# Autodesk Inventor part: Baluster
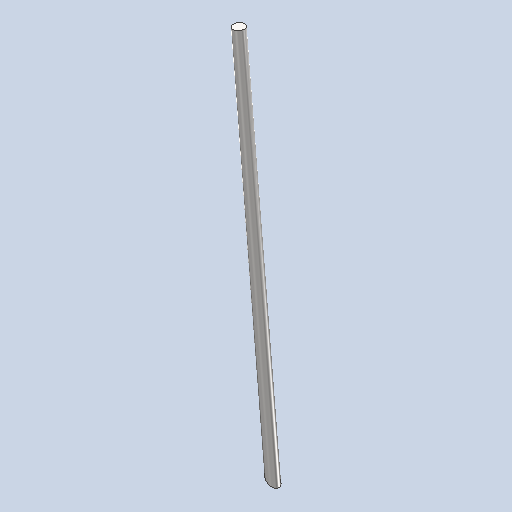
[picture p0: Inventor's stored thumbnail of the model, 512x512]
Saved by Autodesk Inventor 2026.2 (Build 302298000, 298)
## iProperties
Created: 2022-06
Part Number: Baluster
Material: Steel, Galvanized
Document SubType Name: Modeling
Designer: reaumed
Density: 7.85 g/cm^3
Appearance: Galvanized
Mass: 3323.97 g
Surface Area: 678.138 cm^2
Volume: 423.435 cm^3
Author: reaumed
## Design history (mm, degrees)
workplane "Work Plane1"
workplane "Work Plane2"
workplane "Work Plane3"
sketch "Sketch1"
  geometry: L1 (-1199.072, 361.95)-(1779.005, 361.95) reference; L2 (114.3, 449.58)-(114.3, -74.93) reference; C1 r 12.7 at (114.3, 361.95); 1 further point
  constraints: 1 centre point
  dimensions: "d3" = 0 distance from line of C1.centre L1; "d4" = 0 distance from line of L2 C1.centre; "d7" = 25.4 diameter of C1 (= BalusterDia)
extrude "Extrusion1" new body sketch "Sketch1" distance "d5" = 927.1 (= BalusterLength + 0.5 x BalusterDia); taper "d6" = 0 deg
sketch "Sketch2"
  geometry: L1 (-228.6, -190.5)-(-1353.565, -1127.971); L2 (0, -190.5)-(-228.6, -190.5); L3 (773.632, -1127.971)-(-1353.565, -1127.971); 1 further point
  constraints: 6 end point, 2 horizontal
  dimensions: "d8" = 190.5 distance from line of L2 point (0, 0) (= Rise); "d9" = 228.6 horizontal distance of L1.start point (0, 0) (= Run); "d10" = 39.8056 deg angle of L3 L1 (= TheAngle)
workplane "Work Plane7"
split "Split4"
body "Solid1"
other parameters: "Rise" = 190.5 [user parameter; used in 2 equation terms], "Run" = 228.6 [user parameter; used in 2 equation terms], "Width" = 762 [user parameter; used in 1 equation term], "d0" = -190.5 (= -Rise), "d1" = 361.95 (= 0.5 x Width - 0.5 x StringerThickness), "d2" = 114.3 (= 0.5 x Run), "BalusterDia" = 25.4 [user parameter; used in 2 equation terms], "BalusterLength" = 914.4 [user parameter; used in 1 equation term], "StringerThickness" = 38.1 [user parameter; used in 1 equation term], "TreadThickness" = 31.75 [user parameter], "d11" = 90 deg, "TheAngle" = 39.8056 deg [user parameter; used in 1 equation term]
